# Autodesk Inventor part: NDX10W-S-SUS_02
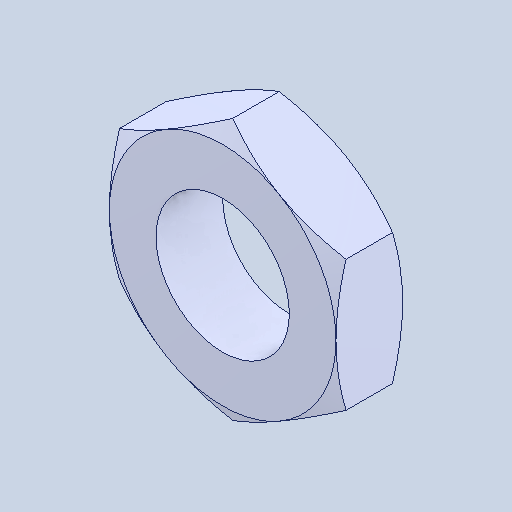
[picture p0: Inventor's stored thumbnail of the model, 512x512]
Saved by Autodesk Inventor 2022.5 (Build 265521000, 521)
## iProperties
Created: 2024-05
Part Number: NDX10W-S-SUS_02
Material: 一般
Document SubType Name: Modeling
Designer: ImaoCorp
Density: 1 g/cm^3
Appearance: 既定
Author: ImaoCorp
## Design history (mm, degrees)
feature "NDX10W-S-SUS_02"
node "ソリッド1"
